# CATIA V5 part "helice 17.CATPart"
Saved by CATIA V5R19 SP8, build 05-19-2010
Part number: helice 17
Bounding box of the stored display mesh (mm): x -17.321 to 17.321, y -30 to 195, z -10 to 20
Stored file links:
  G:\EU_thinkMotion\CFAO_2010\MMS_groupe2\MMS_groupe2\A reprendre\splanchenault\Planchenault\helice 17.CATPart
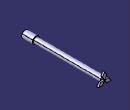
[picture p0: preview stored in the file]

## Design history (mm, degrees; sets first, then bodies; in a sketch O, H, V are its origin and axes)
Body1 (main body)
  Sketch1 on xy-plane, origin (0, 0, 0), H (1, 0, 0), V (0, 1, 0)
    line L1 (0, 0) -> (0, -30)
    line L2 (0, -30) -> (10, -30)
    line L3 (10, -30) -> (10, 0)
    line L4 (10, 0) -> (7.5, 0)
    line L5 (7.5, 0) -> (7.5, 190)
    line L6 (7.5, 190) -> (0, 190)
    point P6 (0, 190)
    line L7 (0, 190) -> (0, 0)
    length L6 = 7.5
    vertical: L1 V, L3 V, L5 V, L7 V
    horizontal: L2 H, L4 H, L6 H
    coincidence: P6 V
  Shaft1: profile Sketch1, axis Sketch1.L1, angle 360
  Sketch2 on face of Shaft1 from Sketch1.L6, origin (0, 190, 0), H (-1, 0, 0), V (0, 0, 1)
    construction line L1 (19.3649, -11.1803) -> (-19.3649, 11.1803)
    axis line L2 (-18.8746, -10.8972) -> (18.8746, 10.8972)
    line L3 (0, 0) -> (5.7735, 10)
    point P5 (5.7735, 10)
    line L4 (5.7735, 10) -> (0, 20)
    point P6 (0, 20)
    line L5 (0, 20) -> (-5.7735, 10)
    point P7 (-5.7735, 10)
    line L6 (-5.7735, 10) -> (0, 0)
    point P8 (-11.547, 0)
    point P9 (-17.3205, -10)
    line L7 (-17.3205, -10) -> (-11.547, 0)
    point P10 (-5.7735, -10)
    line L8 (-5.7735, -10) -> (-17.3205, -10)
    point P11 (0, 0)
    line L9 (0, 0) -> (-5.7735, -10)
    line L10 (-11.547, 0) -> (0, 0)
    point P12 (5.7735, -10)
    point P13 (17.3205, -10)
    line L11 (17.3205, -10) -> (5.7735, -10)
    point P14 (11.547, 0)
    line L12 (11.547, 0) -> (17.3205, -10)
    point P15 (0, 0)
    line L13 (0, 0) -> (11.547, 0)
    line L14 (5.7735, -10) -> (0, 0)
    angle L1 V = 60
    angle L2 V = 60
    coincidence: L1 O, P6 V, O P11, O P15, P11 P15
    perpendicularity: L3 L1, L4 L2
    parallelism: L5 L3, L6 L4
    symmetry: P7 P8 L1, P6 P9 L1, L5 L7 L1, P5 P10 L1, L4 L8 L1, O P11 L1, L3 L9 L1, L6 L10 L1, P7 P12 L2, P6 P13 L2, L5 L11 L2, P5 P14 L2, L4 L12 L2, O P15 L2, L3 L13 L2, L6 L14 L2
  Pad1: profile Sketch2, direction (0, 1, 0), length 5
